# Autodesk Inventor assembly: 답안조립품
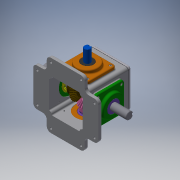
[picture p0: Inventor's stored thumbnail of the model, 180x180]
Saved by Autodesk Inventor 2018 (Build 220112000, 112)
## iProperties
Created: 2019-12
Part Number: 답안조립품
Document SubType Name: Assembly
Designer: Administrator
Author: Administrator
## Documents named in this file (16)
- C:\Users\Administrator\Desktop\391204v1071\답안조립품.iam
- C:\Users\Administrator\Desktop\391204v1071\본체.ipt
- C:\Users\Administrator\Desktop\391204v1071\메인커버.ipt
- C:\Users\Administrator\Desktop\391204v1071\서브커버.ipt
- C:\Users\Administrator\Desktop\391204v1071\베어링 6204.ipt
- C:\Users\Administrator\Desktop\391204v1071\베어링 6203.ipt
- C:\Users\Administrator\Desktop\391204v1071\메인축.ipt
- C:\Users\Administrator\Desktop\391204v1071\키 4x4.ipt
- C:\Users\Administrator\Desktop\391204v1071\메인베벨기어.ipt
- C:\Users\Administrator\Desktop\391204v1071\오일 실 20 35 8.ipt
- C:\Users\Administrator\Desktop\391204v1071\서브축.ipt
- C:\Users\Administrator\Desktop\391204v1071\서브베벨기어.ipt
- C:\Users\Administrator\Desktop\391204v1071\오일 실 17 32 8.ipt
- C:\Users\Administrator\Desktop\391204v1071\개스킷.ipt
- C:\Users\Administrator\Desktop\391204v1071\상부커버.ipt
- C:\Users\Administrator\Desktop\391204v1071\볼트 M4.ipt
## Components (1 placed, 1 different names)
1. 개스킷:1
